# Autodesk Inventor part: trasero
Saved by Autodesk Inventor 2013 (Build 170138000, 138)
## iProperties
Created: 2013-03
Part Number: trasero
Material: Generic
Document SubType Name: Modeling
Designer: julian.chica
Density: 1 g/cm^3
Author: julian.chica
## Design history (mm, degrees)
derived "Parlante_INICIAL.ipt"
feature "trasero::Parlante_INICIAL.ipt" dims "d0" = 10
tag "TaggingFeature1"
body "Solid1"
